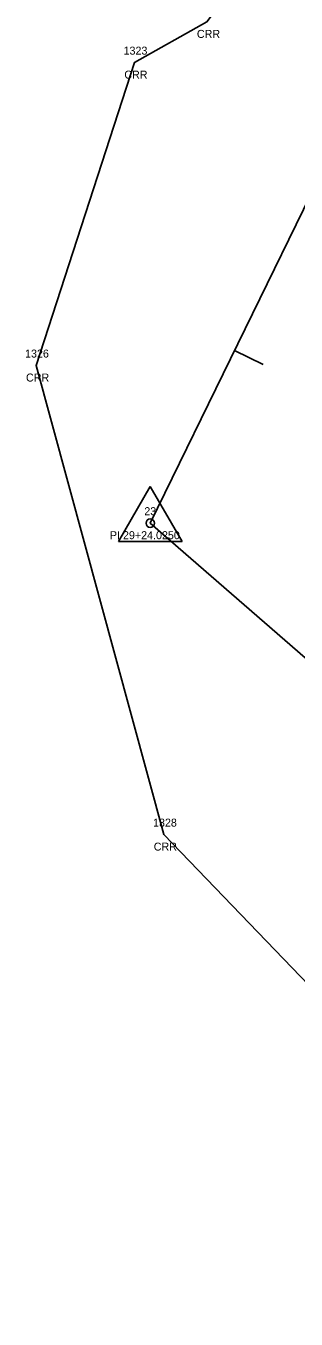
# Model space of a CAD drawing. Extents: x 1964982 to 1970527, y 1116335 to 1119906.
# Drawn here: x 1967713.8 to 1967747.5, y 1117454.2 to 1117615.8 of the extents above; entities that cross this region are included whole.
import ezdxf

# ---------------------------------------------------------------- set-up
doc = ezdxf.new("R2010")
doc.units = 0
for name, color, linetype in [('RD_EX_H2O', 7, 'Continuous'), ('RD_EX_H2O_txCode', 7, 'Continuous'), ('RD_HC_CL', 7, 'Continuous'), ('RD_HC_Data', 7, 'Continuous'), ('RD_HC_Data_Tic', 7, 'Continuous'), ('RD_HC_txCode', 7, 'Continuous'), ('RD_SMD_Locator', 7, 'Continuous')]:
    doc.layers.add(name, color=color, linetype=linetype)

msp = doc.modelspace()

# ---------------------------------------------------------------- linework, layer by layer
at = {"layer": 'RD_EX_H2O'}
msp.add_lwpolyline([(1967794.3, 1117875.45), (1967796.63, 1117853.43), (1967809.67, 1117835.4), (1967828.83, 1117808.28), (1967805.08, 1117754.56), (1967786.33, 1117708.04), (1967780.19, 1117689.35), (1967762.68, 1117651.19), (1967736.39, 1117616.3), (1967727.33, 1117611.21), (1967715.04, 1117573.35), (1967731.01, 1117514.73), (1967775.86, 1117468.11), (1967793.29, 1117458.88), (1967816.39, 1117454.18)], dxfattribs=at)
at = {"layer": 'RD_HC_CL'}
for p, q in [((1967849.81, 1117800.6), (1967729.31, 1117553.65)), ((1967729.31, 1117553.65), (1967830.8, 1117465.42))]:
    msp.add_line(p, q, dxfattribs=at)
at = {"layer": 'RD_HC_Data'}
for p, q in [((1967725.33, 1117551.36), (1967729.31, 1117558.24)), ((1967729.31, 1117558.24), (1967733.28, 1117551.36)), ((1967725.33, 1117551.36), (1967733.28, 1117551.36))]:
    msp.add_line(p, q, dxfattribs=at)
msp.add_circle((1967729.31, 1117553.65), 0.529, dxfattribs=at)
at = {"layer": 'RD_HC_Data_Tic'}
msp.add_line((1967739.84, 1117575.25), (1967743.44, 1117573.49), dxfattribs=at)
at = {"layer": 'RD_SMD_Locator'}
for centre in [(1967727.33, 1117611.21), (1967715.04, 1117573.35), (1967729.31, 1117553.65), (1967731.01, 1117514.73)]:
    msp.add_circle(centre, 0.001, dxfattribs=at)

# ---------------------------------------------------------------- texts
at = {"layer": 'RD_EX_H2O_txCode'}
for s, p in [('CRR', (1967735.14, 1117614.3)), ('1323', (1967725.98, 1117612.21)), ('CRR', (1967726.07, 1117609.21)), ('1326', (1967713.67, 1117574.35)), ('CRR', (1967713.79, 1117571.35)), ('1328', (1967729.66, 1117515.73)), ('CRR', (1967729.75, 1117512.73))]:
    msp.add_text(s, height=1, dxfattribs=at).set_placement(p)
at = {"layer": 'RD_HC_txCode'}
for s, p in [('23', (1967728.57, 1117554.65)), ('PI 29+24.0250', (1967724.27, 1117551.65))]:
    msp.add_text(s, height=1, dxfattribs=at).set_placement(p)

doc.saveas('drawing.dxf')
